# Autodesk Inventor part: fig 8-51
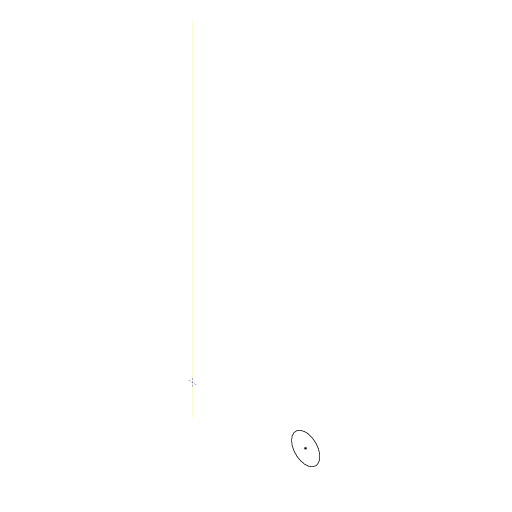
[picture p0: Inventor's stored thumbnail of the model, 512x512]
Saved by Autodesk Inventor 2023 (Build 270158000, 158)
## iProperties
Created: 2002-01
Part Number: fig 8-51
Document SubType Name: Modeling
Designer: CADSoft
Density: 1 g/cm^3
Material: Generic
Appearance: Default
Control State: 0
Master: False
Checked Out: False
Shininess: 77.0
Length Units: 11269
Angle Units: 11279
Time Units: 11290
Mass Units: 11283
Length Display Precision: 3
Angle Display Precision: 2
Density: 0.0
Volumn: 0.0
Area: 0.0
PropertySet Name: Model Information
Author: CADSoft
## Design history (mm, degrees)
sketch "Sketch2"
  geometry: C1 r 2.5 at (-20, -0.092); 1 further point
  constraints: 1 centre point, 2 other
workaxis "Work Axis1"
body "Solid1"
